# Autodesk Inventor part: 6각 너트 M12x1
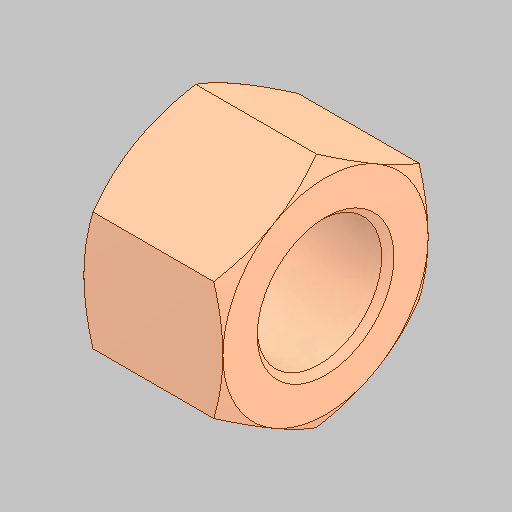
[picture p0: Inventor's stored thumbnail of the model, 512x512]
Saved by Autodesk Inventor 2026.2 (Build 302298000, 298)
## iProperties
Created: 2026-06
Part Number: 6각 너트 M12x1
Material: 강철, 연강
Description: 6각 너트 및 6각 가는 너트
Document SubType Name: Modeling
Designer: sec7
Density: 7.85 g/cm^3
Appearance: 기본값
Author: jhkim
Sending System: Autodesk Inventor 2027
Preprocessor: ST-DEVELOPER v20.1
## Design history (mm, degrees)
feature "Solid1"
node "솔리드1"
